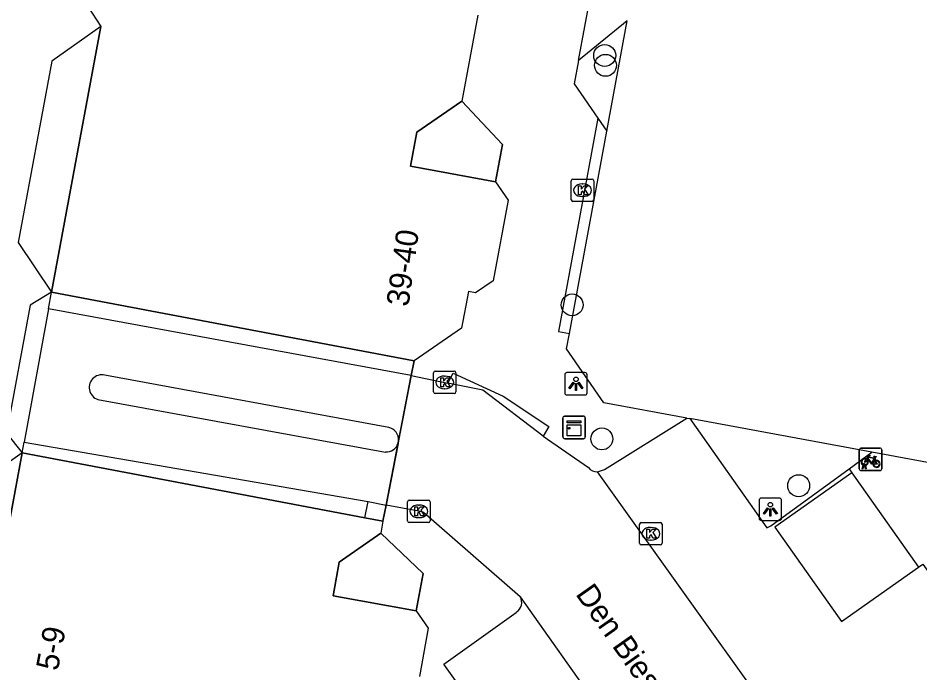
# Model space of a CAD drawing. Extents: x 161845 to 162341, y 381620 to 382158.
# Drawn here: x 161927.1 to 161967.29, y 382012.07 to 382041.26 of the extents above; entities that cross this region are included whole.
import ezdxf

# ---------------------------------------------------------------- set-up
doc = ezdxf.new("R2010")
doc.units = 0
for name, color, linetype in [('IMGEO_Boom', 7, 'Continuous'), ('IMGEO_Fietsenrek', 7, 'Continuous'), ('IMGEO_Groenvoorziening', 7, 'Continuous'), ('IMGEO_Kast', 7, 'Continuous'), ('IMGEO_Kolk', 7, 'Continuous'), ('IMGEO_Lichtpunt', 7, 'Continuous'), ('IMGEO_Openbare_ruimte_label', 7, 'Continuous'), ('IMGEO_Pand', 7, 'Continuous'), ('IMGEO_Pand_nummerreeks', 7, 'Continuous'), ('IMGEO_Pand_overbouw', 7, 'Continuous'), ('IMGEO_Parkeervlak_open', 7, 'Continuous'), ('IMGEO_Rijbaan_lokaal_open', 7, 'Continuous'), ('IMGEO_Voetpad_open', 7, 'Continuous')]:
    doc.layers.add(name, color=color, linetype=linetype)

msp = doc.modelspace()

# ---------------------------------------------------------------- linework, layer by layer
at = {"layer": 'IMGEO_Boom'}
for centre in [(161953.242, 382039.588), (161953.275, 382039.151), (161951.79, 382028.476), (161953.114, 382022.504), (161961.884, 382020.418)]:
    msp.add_circle(centre, 0.489, dxfattribs=at)
at = {"layer": 'IMGEO_Fietsenrek'}
for p, q in [((161964.586, 382021.166), (161964.586, 382022.007)), ((161964.586, 382022.007), (161964.586, 382021.166)), ((161964.661, 382022.091), (161965.502, 382022.091)), ((161965.502, 382022.091), (161964.661, 382022.091)), ((161965.586, 382022.016), (161965.586, 382021.175)), ((161965.586, 382021.175), (161965.586, 382022.016)), ((161965.273, 382021.64), (161965.309, 382021.545)), ((161965.511, 382021.091), (161964.67, 382021.091)), ((161964.67, 382021.091), (161965.511, 382021.091)), ((161964.713, 382021.175), (161964.752, 382021.335)), ((161964.747, 382021.175), (161964.713, 382021.175)), ((161964.782, 382021.323), (161964.747, 382021.175)), ((161964.824, 382021.347), (161964.823, 382021.351)), ((161964.865, 382021.175), (161964.831, 382021.317)), ((161964.855, 382021.358), (161964.856, 382021.351)), ((161964.863, 382021.321), (161964.898, 382021.175)), ((161964.898, 382021.175), (161964.865, 382021.175))]:
    msp.add_line(p, q, dxfattribs=at)
for points in [[(161964.92, 382021.565), (161964.868, 382021.475), (161964.828, 382021.45), (161964.829, 382021.497), (161964.884, 382021.591)], [(161964.899, 382021.617), (161964.994, 382021.781), (161965.08, 382021.767), (161965.082, 382021.758), (161965.026, 382021.747), (161964.999, 382021.702), (161965.255, 382021.661)], [(161965.195, 382021.373), (161965.145, 382021.373), (161964.954, 382021.624), (161964.935, 382021.592)], [(161965.242, 382021.636), (161964.985, 382021.677), (161964.968, 382021.648), (161965.135, 382021.428), (161965.242, 382021.636)], [(161965.29, 382021.538), (161965.26, 382021.615), (161965.151, 382021.397), (161965.194, 382021.397)], [(161965.224, 382021.397), (161965.344, 382021.396), (161965.3, 382021.51)], [(161965.32, 382021.517), (161965.375, 382021.372), (161965.225, 382021.372)], [(161965.255, 382021.661), (161965.28, 382021.71), (161965.274, 382021.714), (161965.251, 382021.718), (161965.239, 382021.725), (161965.238, 382021.728), (161965.24, 382021.733), (161965.335, 382021.718), (161965.337, 382021.708), (161965.327, 382021.695), (161965.315, 382021.689), (161965.301, 382021.695), (161965.273, 382021.64)]]:
    msp.add_lwpolyline(points, dxfattribs=at)
for centre, radius, start, end in [((161964.664, 382022.013), 0.0779, 92.4484, 184.2845), ((161964.664, 382022.013), 0.0779, 92.4484, 184.2845), ((161965.508, 382022.013), 0.0779, 2.4484, 94.2845), ((161965.508, 382022.013), 0.0779, 2.4484, 94.2845), ((161964.826, 382021.476), 0.159, 62.6766, 242.1369), ((161964.826, 382021.476), 0.129, 63.3192, 238.903), ((161964.826, 382021.476), 0.129, 283.6043, 43.4302), ((161964.826, 382021.476), 0.159, 283.5766, 46.6042), ((161965.353, 382021.392), 0.159, 113.3408, 178.3217), ((161965.353, 382021.392), 0.159, 187.0065, 105.7708), ((161965.353, 382021.392), 0.129, 113.923, 177.9556), ((161965.353, 382021.392), 0.129, 188.6715, 104.5883), ((161964.664, 382021.169), 0.0779, 182.4484, 274.2845), ((161964.664, 382021.169), 0.0779, 182.4484, 274.2845), ((161964.806, 382021.347), 0.0499, 12.8025, 158.6934), ((161964.826, 382021.476), 0.159, 253.9967, 271.7867), ((161964.806, 382021.347), 0.0174, 12.8025, 163.4502), ((161964.826, 382021.476), 0.129, 253.415, 269.0204), ((161965.508, 382021.169), 0.0779, 272.4484, 4.2845), ((161965.508, 382021.169), 0.0779, 272.4484, 4.2845)]:
    msp.add_arc(centre, radius, start, end, dxfattribs=at)
at = {"layer": 'IMGEO_Groenvoorziening'}
msp.add_lwpolyline([(161952.931, 382036.799), (161953.332, 382036.216)], dxfattribs=at)
at = {"layer": 'IMGEO_Kast'}
for p, q in [((161951.376, 382022.589), (161951.376, 382023.43)), ((161951.376, 382023.43), (161951.376, 382022.589)), ((161951.451, 382023.514), (161952.292, 382023.514)), ((161952.292, 382023.514), (161951.451, 382023.514)), ((161952.376, 382023.439), (161952.376, 382022.598)), ((161952.376, 382022.598), (161952.376, 382023.439)), ((161952.301, 382022.514), (161951.46, 382022.514)), ((161951.46, 382022.514), (161952.301, 382022.514))]:
    msp.add_line(p, q, dxfattribs=at)
for points in [[(161951.571, 382023.304), (161952.171, 382023.304), (161952.171, 382023.219), (161951.571, 382023.219), (161951.571, 382023.304)], [(161951.571, 382023.129), (161952.171, 382023.129), (161952.171, 382022.64), (161951.571, 382022.64), (161951.571, 382023.129)]]:
    msp.add_lwpolyline(points, dxfattribs=at)
msp.add_circle((161951.655, 382022.978), 0.0377, dxfattribs=at)
for centre, start, end in [((161951.454, 382023.436), 92.4484, 184.2845), ((161951.454, 382023.436), 92.4484, 184.2845), ((161952.298, 382023.436), 2.4484, 94.2845), ((161952.298, 382023.436), 2.4484, 94.2845), ((161951.454, 382022.592), 182.4484, 274.2845), ((161951.454, 382022.592), 182.4484, 274.2845), ((161952.298, 382022.592), 272.4484, 4.2845), ((161952.298, 382022.592), 272.4484, 4.2845)]:
    msp.add_arc(centre, 0.0779, start, end, dxfattribs=at)
at = {"layer": 'IMGEO_Kolk'}
for p, q in [((161951.751, 382033.158), (161951.751, 382034.01)), ((161951.826, 382034.084), (161952.678, 382034.084)), ((161952.752, 382034.01), (161952.752, 382033.158)), ((161952.239, 382033.864), (161952.264, 382033.864)), ((161952.678, 382033.084), (161951.826, 382033.084)), ((161952.262, 382033.304), (161952.237, 382033.304)), ((161945.611, 382024.596), (161945.611, 382025.448)), ((161945.686, 382025.522), (161946.538, 382025.522)), ((161946.612, 382025.448), (161946.612, 382024.596)), ((161946.099, 382025.302), (161946.124, 382025.302)), ((161946.122, 382024.742), (161946.097, 382024.742)), ((161946.538, 382024.522), (161945.686, 382024.522)), ((161944.459, 382018.852), (161944.459, 382019.704)), ((161944.534, 382019.778), (161945.386, 382019.778)), ((161944.947, 382019.558), (161944.972, 382019.558)), ((161945.46, 382019.704), (161945.46, 382018.852)), ((161945.386, 382018.778), (161944.534, 382018.778)), ((161944.97, 382018.998), (161944.945, 382018.998)), ((161954.797, 382017.852), (161954.797, 382018.704)), ((161954.872, 382018.778), (161955.724, 382018.778)), ((161955.798, 382018.704), (161955.798, 382017.852)), ((161955.285, 382018.558), (161955.31, 382018.558)), ((161955.308, 382017.998), (161955.283, 382017.998)), ((161955.724, 382017.778), (161954.872, 382017.778))]:
    msp.add_line(p, q, dxfattribs=at)
for points in [[(161951.751, 382033.158), (161951.751, 382034.01)], [(161951.826, 382034.084), (161952.678, 382034.084)], [(161952.752, 382034.01), (161952.752, 382033.158)], [(161952.072, 382033.784), (161952.195, 382033.784), (161952.195, 382033.633), (161952.325, 382033.784), (161952.489, 382033.784), (161952.343, 382033.633), (161952.496, 382033.384), (161952.344, 382033.384), (161952.259, 382033.548), (161952.195, 382033.481), (161952.195, 382033.384), (161952.072, 382033.384), (161952.072, 382033.784)], [(161952.678, 382033.084), (161951.826, 382033.084)], [(161945.611, 382024.596), (161945.611, 382025.448)], [(161945.686, 382025.522), (161946.538, 382025.522)], [(161946.612, 382025.448), (161946.612, 382024.596)], [(161945.932, 382025.222), (161946.055, 382025.222), (161946.055, 382025.071), (161946.185, 382025.222), (161946.349, 382025.222), (161946.203, 382025.071), (161946.356, 382024.822), (161946.204, 382024.822), (161946.119, 382024.986), (161946.055, 382024.919), (161946.055, 382024.822), (161945.932, 382024.822), (161945.932, 382025.222)], [(161946.538, 382024.522), (161945.686, 382024.522)], [(161944.459, 382018.852), (161944.459, 382019.704)], [(161944.534, 382019.778), (161945.386, 382019.778)], [(161944.78, 382019.478), (161944.903, 382019.478), (161944.903, 382019.327), (161945.033, 382019.478), (161945.197, 382019.478), (161945.051, 382019.327), (161945.204, 382019.078), (161945.052, 382019.078), (161944.967, 382019.242), (161944.903, 382019.175), (161944.903, 382019.078), (161944.78, 382019.078), (161944.78, 382019.478)], [(161945.46, 382019.704), (161945.46, 382018.852)], [(161945.386, 382018.778), (161944.534, 382018.778)], [(161954.797, 382017.852), (161954.797, 382018.704)], [(161954.872, 382018.778), (161955.724, 382018.778)], [(161955.798, 382018.704), (161955.798, 382017.852)], [(161955.118, 382018.478), (161955.241, 382018.478), (161955.241, 382018.327), (161955.371, 382018.478), (161955.535, 382018.478), (161955.389, 382018.327), (161955.542, 382018.078), (161955.39, 382018.078), (161955.305, 382018.242), (161955.241, 382018.175), (161955.241, 382018.078), (161955.118, 382018.078), (161955.118, 382018.478)], [(161955.724, 382017.778), (161954.872, 382017.778)]]:
    msp.add_lwpolyline(points, dxfattribs=at)
for centre, start, end in [((161951.828, 382034.008), 91.552, 178.448), ((161951.828, 382034.008), 91.552, 178.448), ((161952.676, 382034.008), 1.552, 88.448), ((161952.676, 382034.008), 1.552, 88.448), ((161951.828, 382033.16), 181.552, 268.448), ((161951.828, 382033.16), 181.552, 268.448), ((161952.676, 382033.16), 271.552, 358.448), ((161952.676, 382033.16), 271.552, 358.448), ((161945.688, 382025.446), 91.552, 178.448), ((161945.688, 382025.446), 91.552, 178.448), ((161946.536, 382025.446), 1.552, 88.448), ((161946.536, 382025.446), 1.552, 88.448), ((161945.688, 382024.598), 181.552, 268.448), ((161945.688, 382024.598), 181.552, 268.448), ((161946.536, 382024.598), 271.552, 358.448), ((161946.536, 382024.598), 271.552, 358.448), ((161944.536, 382019.702), 91.552, 178.448), ((161944.536, 382019.702), 91.552, 178.448), ((161945.384, 382019.702), 1.552, 88.448), ((161945.384, 382019.702), 1.552, 88.448), ((161944.536, 382018.854), 181.552, 268.448), ((161944.536, 382018.854), 181.552, 268.448), ((161945.384, 382018.854), 271.552, 358.448), ((161945.384, 382018.854), 271.552, 358.448), ((161954.874, 382018.702), 91.552, 178.448), ((161954.874, 382018.702), 91.552, 178.448), ((161955.722, 382018.702), 1.552, 88.448), ((161955.722, 382018.702), 1.552, 88.448), ((161954.874, 382017.854), 181.552, 268.448), ((161954.874, 382017.854), 181.552, 268.448), ((161955.722, 382017.854), 271.552, 358.448), ((161955.722, 382017.854), 271.552, 358.448)]:
    msp.add_arc(centre, 0.0765, start, end, dxfattribs=at)
for centre, major_axis, ratio, start_param, end_param in [((161952.238, 382033.584), (-0.387, 0.002), 0.722429, 4.712389, 7.853982), ((161952.263, 382033.584), (-0.39, 0.002), 0.717154, 1.570796, 4.712389), ((161946.098, 382025.022), (-0.387, 0.002), 0.722429, 4.712389, 7.853982), ((161946.123, 382025.022), (-0.39, 0.002), 0.717154, 1.570796, 4.712389), ((161944.946, 382019.278), (-0.387, 0.002), 0.722429, 4.712389, 7.853982), ((161944.971, 382019.278), (-0.39, 0.002), 0.717154, 1.570796, 4.712389), ((161955.284, 382018.278), (-0.387, 0.002), 0.722429, 4.712389, 7.853982), ((161955.309, 382018.278), (-0.39, 0.002), 0.717154, 1.570796, 4.712389)]:
    msp.add_ellipse(centre, major_axis=major_axis, ratio=ratio, start_param=start_param, end_param=end_param, dxfattribs=at)
at = {"layer": 'IMGEO_Lichtpunt'}
for p, q in [((161952.362, 382025.457), (161951.554, 382025.457)), ((161952.362, 382025.457), (161951.554, 382025.457)), ((161951.46, 382025.362), (161951.46, 382024.555)), ((161951.46, 382025.362), (161951.46, 382024.555)), ((161952.456, 382024.555), (161952.456, 382025.362)), ((161952.456, 382024.555), (161952.456, 382025.362)), ((161951.554, 382024.461), (161952.362, 382024.461)), ((161951.554, 382024.461), (161952.362, 382024.461)), ((161961.025, 382019.868), (161960.217, 382019.868)), ((161961.025, 382019.868), (161960.217, 382019.868)), ((161960.123, 382019.773), (161960.123, 382018.966)), ((161960.123, 382019.773), (161960.123, 382018.966)), ((161961.119, 382018.966), (161961.119, 382019.773)), ((161961.119, 382018.966), (161961.119, 382019.773)), ((161960.217, 382018.872), (161961.025, 382018.872)), ((161960.217, 382018.872), (161961.025, 382018.872))]:
    msp.add_line(p, q, dxfattribs=at)
for points in [[(161951.834, 382025.026), (161951.873, 382024.998), (161951.685, 382024.736), (161951.647, 382024.763), (161951.834, 382025.026)], [(161951.936, 382024.978), (161951.983, 382024.978), (161951.983, 382024.656), (161951.936, 382024.656), (161951.936, 382024.978)], [(161952.046, 382024.998), (161952.084, 382025.025), (161952.271, 382024.763), (161952.232, 382024.735), (161952.046, 382024.998)], [(161960.497, 382019.437), (161960.536, 382019.409), (161960.348, 382019.147), (161960.31, 382019.174), (161960.497, 382019.437)], [(161960.709, 382019.409), (161960.747, 382019.436), (161960.934, 382019.174), (161960.895, 382019.146), (161960.709, 382019.409)], [(161960.599, 382019.389), (161960.646, 382019.389), (161960.646, 382019.067), (161960.599, 382019.067), (161960.599, 382019.389)]]:
    msp.add_lwpolyline(points, dxfattribs=at)
for centre in [(161951.959, 382025.16), (161960.622, 382019.571)]:
    msp.add_circle(centre, 0.0994, dxfattribs=at)
for centre, start, end in [((161951.554, 382025.362), 90, 180), ((161951.554, 382025.362), 90, 180), ((161952.362, 382025.362), 0, 90), ((161952.362, 382025.362), 0, 90), ((161951.554, 382024.555), 180, 270), ((161951.554, 382024.555), 180, 270), ((161952.362, 382024.555), 270, 0), ((161952.362, 382024.555), 270, 360), ((161960.217, 382019.773), 90, 180), ((161960.217, 382019.773), 90, 180), ((161961.025, 382019.773), 0, 90), ((161961.025, 382019.773), 0, 90), ((161960.217, 382018.966), 180, 270), ((161960.217, 382018.966), 180, 270), ((161961.025, 382018.966), 270, 0), ((161961.025, 382018.966), 270, 360)]:
    msp.add_arc(centre, 0.0946, start, end, dxfattribs=at)
at = {"layer": 'IMGEO_Pand'}
for points in [[(161930.72, 382044.512), (161930.212, 382041.772), (161930.789, 382040.881), (161928.594, 382029.042)], [(161952.069, 382039.362), (161952.63, 382042.405), (161953.421, 382042.949)], [(161947.585, 382041.384), (161946.88, 382037.56)], [(161953.332, 382036.216), (161954.238, 382041.133), (161952.069, 382039.362)], [(161948.379, 382033.955), (161944.593, 382034.653), (161944.875, 382036.179), (161946.88, 382037.56)], [(161951.671, 382027.204), (161953.332, 382036.216)], [(161948.379, 382033.955), (161948.935, 382033.148), (161948.271, 382029.548), (161947.489, 382029.01), (161947.166, 382029.069), (161946.866, 382027.443), (161944.746, 382025.983)], [(161928.594, 382029.042), (161944.746, 382025.983)], [(161956.903, 382023.432), (161953.198, 382024.115), (161951.544, 382026.516), (161951.671, 382027.204)], [(161956.903, 382023.432), (161957.035, 382023.407)], [(161965.144, 382021.912), (161957.035, 382023.407)], [(161969.443, 382022.281), (161969.236, 382021.157), (161965.144, 382021.912)], [(161927.279, 382021.88), (161925.09, 382010.026), (161924.219, 382009.712), (161923.584, 382006.197)], [(161942.549, 382018.993), (161927.279, 382021.88)], [(161964.254, 382020.998), (161960.822, 382018.577), (161963.79, 382014.368), (161967.222, 382016.789)], [(161964.254, 382020.998), (161967.222, 382016.789)], [(161943.358, 382018.84), (161942.549, 382018.993)], [(161943.358, 382018.84), (161943.261, 382018.302)], [(161944.842, 382014.84), (161941.135, 382015.51), (161941.406, 382017.015), (161943.261, 382018.302)], [(161944.842, 382014.84), (161945.38, 382014.065), (161944.993, 382011.92)]]:
    msp.add_lwpolyline(points, dxfattribs=at)
at = {"layer": 'IMGEO_Pand_overbouw'}
for points in [[(161930.789, 382040.881), (161928.602, 382039.344), (161927.104, 382031.261), (161928.594, 382029.042)], [(161946.88, 382037.56), (161944.875, 382036.179), (161944.593, 382034.653), (161948.379, 382033.955), (161948.687, 382035.627)], [(161944.619, 382025.33), (161944.746, 382025.983), (161928.594, 382029.042), (161927.634, 382028.467), (161926.587, 382022.761), (161927.279, 382021.88), (161942.549, 382018.993), (161943.358, 382018.84), (161943.497, 382019.556)], [(161927.279, 382021.88), (161925.094, 382020.343), (161923.598, 382012.245), (161925.09, 382010.026)], [(161943.261, 382018.302), (161941.406, 382017.015), (161941.135, 382015.51), (161944.842, 382014.84), (161945.144, 382016.513)]]:
    msp.add_lwpolyline(points, close=True, dxfattribs=at)
at = {"layer": 'IMGEO_Parkeervlak_open'}
msp.add_lwpolyline([(161957.035, 382023.407), (161960.47, 382018.536), (161960.642, 382018.637), (161964.131, 382021.175)], dxfattribs=at)
at = {"layer": 'IMGEO_Rijbaan_lokaal_open'}
for points in [[(161928.457, 382028.297), (161927.367, 382022.359)], [(161944.619, 382025.33), (161928.457, 382028.297)], [(161943.617, 382023.009), (161931.04, 382025.323)], [(161944.619, 382025.33), (161944.055, 382022.425)], [(161944.619, 382025.33), (161946.249, 382024.993)], [(161950.505, 382022.622), (161947.808, 382024.671), (161946.249, 382024.993)], [(161930.659, 382024.254), (161943.465, 382021.92)], [(161927.367, 382022.359), (161942.704, 382019.707)], [(161944.031, 382022.305), (161943.497, 382019.556)], [(161944.055, 382022.425), (161944.031, 382022.305)], [(161950.505, 382022.622), (161952.514, 382021.226)], [(161964.131, 382021.175), (161965.144, 382021.912)], [(161967.222, 382016.789), (161967.422, 382016.928), (161978.923, 382000.803), (161977.102, 381999.506), (161979.77, 381995.72), (161975.138, 381992.428), (161972.459, 381996.184), (161971.271, 381995.35), (161967.947, 382000), (161952.913, 382021.03)], [(161964.131, 382021.175), (161964.254, 382020.998)], [(161942.704, 382019.707), (161943.497, 382019.556)], [(161949.468, 382015.472), (161945.173, 382019.231), (161944.959, 382019.279), (161943.497, 382019.556)], [(161949.468, 382015.472), (161953.016, 382010.449), (161959.531, 382001.364), (161960.495, 382000), (161966.81, 381991.062), (161968.8, 381988.304), (161965.15, 381985.684), (161964.923, 381986.014)]]:
    msp.add_lwpolyline(points, dxfattribs=at)
for centre, radius, start, end in [((161930.837, 382024.793), 0.568, 68.9947, 251.7724), ((161943.504, 382022.468), 0.552, 355.5034, 78.2364), ((161943.505, 382022.47), 0.551, 265.8426, 342.6054), ((161952.919, 382021.546), 0.516, 218.3307, 269.3461)]:
    msp.add_arc(centre, radius, start, end, dxfattribs=at)
at = {"layer": 'IMGEO_Voetpad_open'}
for points in [[(161952.069, 382039.362), (161951.878, 382038.328), (161952.931, 382036.799)], [(161946.88, 382037.56), (161948.687, 382035.627), (161948.379, 382033.955)], [(161952.931, 382036.799), (161951.179, 382027.295), (161951.671, 382027.204)], [(161928.457, 382028.297), (161928.594, 382029.042)], [(161944.746, 382025.983), (161944.619, 382025.33)], [(161946.249, 382024.993), (161946.495, 382025.428), (161948.718, 382024.413), (161950.751, 382023.057), (161950.505, 382022.622)], [(161952.913, 382021.03), (161953.233, 382021.139), (161956.903, 382023.432)], [(161927.279, 382021.88), (161927.367, 382022.359)], [(161942.549, 382018.993), (161942.704, 382019.707)], [(161943.497, 382019.556), (161943.358, 382018.84)], [(161943.261, 382018.302), (161945.144, 382016.513), (161944.842, 382014.84)], [(161955.8, 382004.634), (161953.047, 382002.674), (161946.075, 382012.46), (161949.3, 382014.775)]]:
    msp.add_lwpolyline(points, dxfattribs=at)
msp.add_arc((161949.031, 382015.209), 0.51, 301.8266, 31.07, dxfattribs=at)

# ---------------------------------------------------------------- texts
at = {"layer": 'IMGEO_Openbare_ruimte_label'}
msp.add_text('Den Biest', height=1, rotation=305.2314, dxfattribs=at).set_placement((161951.914, 382015.588))
at = {"layer": 'IMGEO_Pand_nummerreeks'}
for s, rotation, p in [('39-40', 82.1083, (161944.495, 382028.369)), ('5-9', 79.3302, (161928.871, 382012.134))]:
    msp.add_text(s, height=1, rotation=rotation, dxfattribs=at).set_placement(p)

doc.saveas('drawing.dxf')
